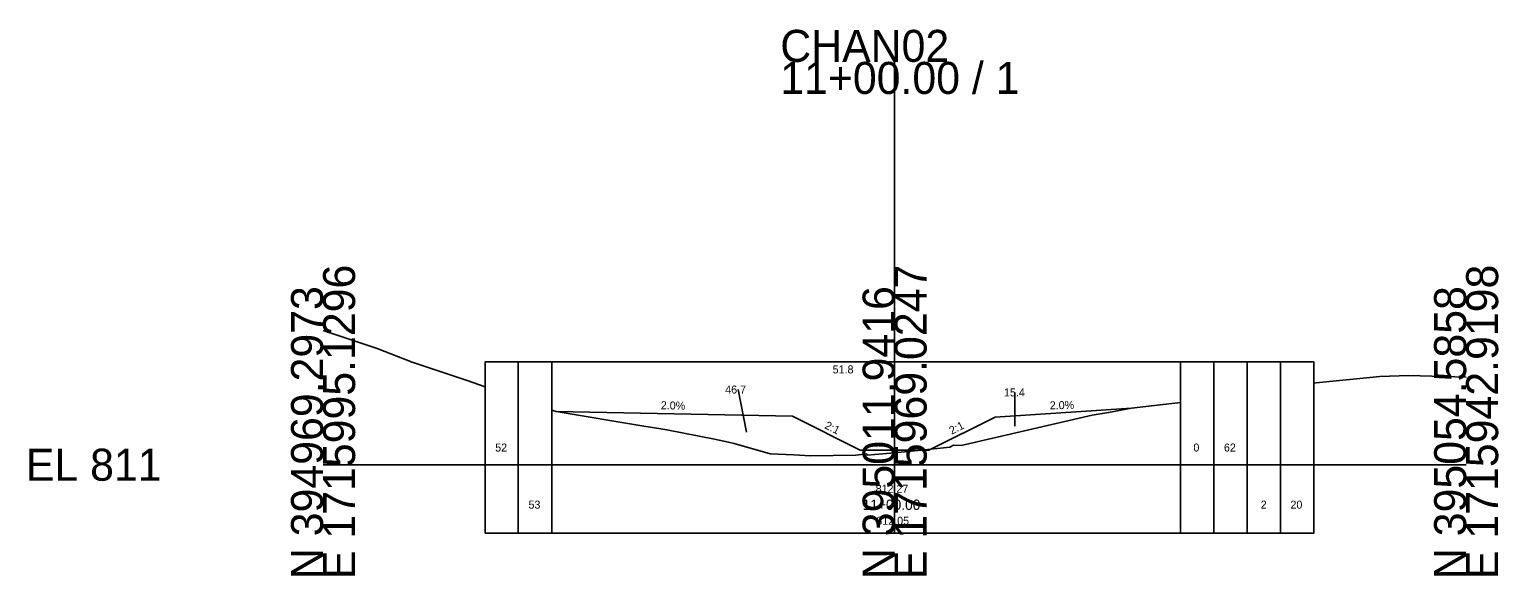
# Model space of a CAD drawing. Extents: x -26 to 103, y -10 to 16052.
# Drawn here: x -25.7 to 102.8, y 11490.3 to 11538.1 of the extents above; entities that cross this region are included whole.
import ezdxf

# ---------------------------------------------------------------- set-up
doc = ezdxf.new("R2010")
doc.units = 0
for name, color, linetype in [('GK_Cells', 7, 'Continuous'), ('SH_Text', 7, 'Continuous'), ('XS_P_Annotation', 7, 'Continuous'), ('XS_P_Boundary', 7, 'Continuous'), ('XS_P_Earthwork_Shapes', 7, 'Continuous'), ('XS_P_Finished_Grade', 7, 'Continuous'), ('XS_X_Ground_Line', 7, 'Continuous')]:
    doc.layers.add(name, color=color, linetype=linetype)

msp = doc.modelspace()

# ---------------------------------------------------------------- linework, layer by layer
at = {"layer": 'GK_Cells'}
for p, q in [((50, 11500), (50, 11535.21)), ((0, 11500), (50, 11500)), ((50, 11500), (100, 11500))]:
    msp.add_line(p, q, dxfattribs=at)
at = {"layer": 'XS_P_Boundary'}
for p, q in [((17.08, 11494.01), (17.08, 11508.99)), ((20, 11494.01), (20, 11508.99)), ((50, 11494.01), (50, 11508.99)), ((75, 11494.01), (75, 11508.99)), ((77.92, 11494.01), (77.92, 11508.99)), ((80.83, 11494.01), (80.83, 11508.99)), ((83.75, 11494.01), (83.75, 11508.99)), ((15.63, 11501.5), (15.63, 11501.5)), ((76.46, 11501.5), (76.46, 11501.5)), ((79.38, 11501.5), (79.38, 11501.5)), ((18.54, 11496.51), (18.54, 11496.51)), ((82.29, 11496.51), (82.29, 11496.51)), ((85.21, 11496.51), (85.21, 11496.51))]:
    msp.add_line(p, q, dxfattribs=at)
msp.add_lwpolyline([(14.17, 11494.01), (14.17, 11508.99), (86.67, 11508.99), (86.67, 11494.01)], close=True, dxfattribs=at)
at = {"layer": 'XS_P_Earthwork_Shapes'}
for p, q in [((37.04, 11502.85), (36.31, 11506.57)), ((60.52, 11503.37), (60.52, 11506.32)), ((41.08, 11504.23), (20.38, 11504.64)), ((47, 11501.27), (41.08, 11504.23)), ((58.79, 11504.16), (53.18, 11501.36)), ((70.72, 11504.93), (58.79, 11504.16)), ((52.32, 11501.27), (47, 11501.27)), ((53.18, 11501.36), (54.84, 11501.53))]:
    msp.add_line(p, q, dxfattribs=at)
for points in [[(20.38, 11504.64), (41.08, 11504.23), (47, 11501.27), (53, 11501.27), (58.79, 11504.16), (70.72, 11504.93)], [(20.38, 11504.64), (28.07, 11503.37), (29.54, 11503.13), (30.08, 11503.04), (34.24, 11502.23), (35.47, 11501.96), (35.95, 11501.84), (39.1, 11500.94), (41.19, 11500.86), (42.63, 11500.79), (46.62, 11500.82), (47.56, 11500.95), (47.59, 11500.82), (48.27, 11500.88), (50, 11501.05), (52.32, 11501.27)], [(54.84, 11501.53), (55.14, 11501.71), (55.83, 11501.68), (67.27, 11504.32), (68.71, 11504.57), (70.72, 11504.93)]]:
    msp.add_lwpolyline(points, dxfattribs=at)
at = {"layer": 'XS_P_Finished_Grade'}
for p, q in [((41.08, 11504.23), (20.38, 11504.64)), ((41.08, 11504.23), (47, 11501.27)), ((58.79, 11504.16), (53, 11501.27)), ((58.79, 11504.16), (70.72, 11504.93)), ((47, 11501.27), (53, 11501.27))]:
    msp.add_line(p, q, dxfattribs=at)
at = {"layer": 'XS_X_Ground_Line'}
for points in [[(0, 11511.74), (4.72, 11510.16), (7.78, 11508.97), (12.6, 11507.36), (14.17, 11506.81)], [(86.67, 11507.13), (86.88, 11507.15), (92.44, 11507.71), (94.99, 11507.81), (100, 11507.65)], [(20, 11504.78), (20.38, 11504.64), (28.07, 11503.37), (29.54, 11503.13), (30.08, 11503.04), (34.24, 11502.23), (35.47, 11501.96), (35.95, 11501.84), (39.1, 11500.94), (41.19, 11500.86), (42.63, 11500.79), (46.62, 11500.82), (47.56, 11500.95), (47.59, 11500.82), (48.27, 11500.88), (50, 11501.05), (52.62, 11501.3), (54.84, 11501.53), (55.14, 11501.71), (55.83, 11501.68), (67.27, 11504.32), (68.71, 11504.57), (70.72, 11504.93), (73.23, 11505.23), (73.23, 11505.23), (74.78, 11505.4), (75, 11505.43)]]:
    msp.add_lwpolyline(points, dxfattribs=at)

# ---------------------------------------------------------------- texts
at = {"layer": 'GK_Cells'}
for s, p in [('CHAN02', (40, 11535.21)), ('11+00.00 / 1', (40, 11532.41)), ('EL 811', (-26, 11498.6))]:
    msp.add_text(s, height=2.8, dxfattribs=at).set_placement(p)
for s, p in [('E 1715995.1296', (2.8, 11490)), ('E 1715969.0247', (52.8, 11490)), ('E 1715942.9198', (102.8, 11490)), ('N 394969.2973', (0, 11490)), ('N 395011.9416', (50, 11490)), ('N 395054.5858', (100, 11490))]:
    msp.add_text(s, height=2.8, rotation=90, dxfattribs=at).set_placement(p)
at = {"layer": 'SH_Text'}
for s, p in [('52', (15.06, 11501.15)), ('0', (76.14, 11501.15)), ('62', (78.81, 11501.15)), ('53', (17.97, 11496.16)), ('2', (82.03, 11496.16)), ('20', (84.63, 11496.16))]:
    msp.add_text(s, height=0.7, dxfattribs=at).set_placement(p)
at = {"layer": 'XS_P_Annotation'}
for s, rotation, p in [('2.0%', 358.8542, (29.54, 11504.85)), ('2.0%', 1.1458, (63.58, 11504.84)), ('2:1', 333.4349, (43.82, 11503.21)), ('2:1', 26.5651, (54.99, 11502.62))]:
    msp.add_text(s, height=0.7, rotation=rotation, dxfattribs=at).set_placement(p)
for s, height, p in [('812.27', 0.7, (48.34, 11497.55)), ('11+00.00', 0.9, (47.2, 11496.05)), ('812.05', 0.7, (48.4, 11494.75))]:
    msp.add_text(s, height=height, dxfattribs=at).set_placement(p)
at = {"layer": 'XS_P_Earthwork_Shapes'}
for s, p in [('51.8', (44.58, 11507.98)), ('46.7', (35.18, 11506.22)), ('15.4', (59.57, 11505.97))]:
    msp.add_text(s, height=0.7, dxfattribs=at).set_placement(p)

doc.saveas('drawing.dxf')
